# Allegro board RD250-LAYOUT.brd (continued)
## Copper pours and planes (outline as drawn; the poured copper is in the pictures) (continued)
SIG00440 on BOTTOM: 262.6,86.25 262.49,86.29 262.45,86.4 262.45,91.15 262.39,91.21 262.36,91.25 262.35,91.31 262.35,91.9 262.39,92.01 262.5,92.05 263.25,92.05 263.36,92.01 263.4,91.9 263.4,91.25 263.76,90.89 264.45,90.89 264.56,90.84 264.6,90.74 264.6,88.76 264.59,88.7 264.56,88.66 263.6,87.7 263.6,86.4 263.56,86.29 263.45,86.25
SIG00445 on TOP: 254.15,80.9 254.04,80.94 254,81.05 254,83.6 251.9,85.7 247.36,85.7 247.3,85.71 247.26,85.74 245.04,87.96 245.01,88 245,88.06 245,94.29 245.01,94.35 245.04,94.39 246.71,96.06 246.75,96.09 246.81,96.1 261.05,96.1 261.16,96.06 261.2,95.95 261.2,91.55 261.16,91.44 261.05,91.4 258.2,91.4 257.25,90.45 257.25,89.8 257.21,89.69 257.1,89.65 254.8,89.65 254.5,89.35 254.5,87.25 255.06,86.69 255.09,86.65 255.1,86.59 255.1,81.05 255.06,80.94 254.95,80.9
SIG00446 on TOP: 244.85,98 244.74,98.04 244.7,98.15 244.7,105 244.74,105.11 244.85,105.15 255.65,105.15 255.76,105.11 255.8,105 255.8,99.8 256.15,99.45 258.21,99.45 259.45,100.12 259.69,100.22 259.95,100.25 261.3,100.25 262.35,99.2 261.3,98.15 259.95,98.15 259.69,98.18 259.45,98.28 258.21,98.95 256.15,98.95 255.8,98.6 255.8,98.15 255.76,98.04 255.65,98
SIG00446 on BOTTOM: 271.06,95.8 271,95.81 270.96,95.84 268.9,97.9 245.36,97.9 245.3,97.91 245.26,97.94 244.59,98.61 244.56,98.65 244.55,98.71 244.55,103.24 244.56,103.3 244.59,103.34 246.36,105.11 246.4,105.14 246.46,105.15 279.54,105.15 279.6,105.14 279.64,105.11 281.41,103.34 281.44,103.3 281.45,103.24 281.45,97.16 281.44,97.1 281.41,97.06 280.19,95.84 280.15,95.81 280.09,95.8
SIG00447 on TOP: 248.16,107.1 248.1,107.11 248.06,107.14 246.29,108.91 246.26,108.95 246.25,109.01 246.25,112.74 246.26,112.8 246.29,112.84 248.01,114.56 248.05,114.59 248.11,114.6 252.6,114.6 254.05,116.05 254.05,117.35 254.09,117.46 254.2,117.5 255,117.5 255.11,117.46 255.15,117.35 255.15,115.1 257.55,112.7 261.05,112.7 261.16,112.66 261.2,112.55 261.2,107.85 261.16,107.74 261.05,107.7 252.2,107.7 251.64,107.14 251.6,107.11 251.54,107.1
SIG00447 on BOTTOM: 248.46,106.7 248.4,106.71 248.36,106.74 245.99,109.11 245.96,109.15 245.95,109.21 245.95,112.84 245.96,112.9 245.99,112.94 247.21,114.16 247.25,114.19 247.31,114.2 253.29,114.2 253.35,114.19 253.39,114.16 255.15,112.4 261.05,112.4 261.16,112.36 261.2,112.25 261.2,106.85 261.16,106.74 261.05,106.7
SIG00448 on TOP: 244.8,59.95 244.69,59.99 244.65,60.1 244.65,66.9 244.69,67.01 244.8,67.05 255.65,67.05 255.76,67.01 255.8,66.9 255.8,61.75 256.2,61.35 258.21,61.35 259.45,62.02 259.69,62.12 259.95,62.15 261.3,62.15 262.35,61.1 261.3,60.05 259.95,60.05 259.69,60.08 259.45,60.18 258.21,60.85 256.2,60.85 255.8,60.45 255.8,60.1 255.76,59.99 255.65,59.95
SIG00449 on BOTTOM: 262.5,106.65 262.39,106.69 262.35,106.8 262.35,107.65 262.39,107.76 262.5,107.8 264.95,107.8 265.06,107.76 265.1,107.65 265.1,106.8 265.06,106.69 264.95,106.65
SIG00449 on BOTTOM: 262.35,113.4 262.24,113.44 262.2,113.55 262.2,116.8 262.24,116.91 262.35,116.95 262.94,116.95 263,116.94 263.04,116.91 265.01,114.94 265.04,114.9 265.05,114.84 265.05,113.55 265.01,113.44 264.9,113.4
SIG00449 on CONDUCTIVE3, CONDUCTIVE4: 262.45,107 262.38,107.03 262.35,107.1 262.35,115 262.38,115.07 262.45,115.1 265.05,115.1 265.12,115.07 265.15,115 265.15,112.95 265.12,112.88 265.05,112.85 264.05,112.85 263.35,112.15 264.05,111.45 265.05,111.45 265.12,111.42 265.15,111.35 265.15,107.1 265.12,107.03 265.05,107
SIG00450 on BOTTOM: 262.35,75.3 262.24,75.34 262.2,75.45 262.2,78.7 262.24,78.81 262.35,78.85 262.94,78.85 263,78.84 263.04,78.81 265.01,76.84 265.04,76.8 265.05,76.74 265.05,75.45 265.01,75.34 264.9,75.3
SIG00450 on BOTTOM: 262.5,68.55 262.39,68.59 262.35,68.7 262.35,69.55 262.39,69.66 262.5,69.7 264.95,69.7 265.06,69.66 265.1,69.55 265.1,68.7 265.06,68.59 264.95,68.55
SIG00450 on CONDUCTIVE3, CONDUCTIVE4: 262.45,68.9 262.38,68.93 262.35,69 262.35,76.9 262.38,76.97 262.45,77 265.05,77 265.12,76.97 265.15,76.9 265.15,74.35 265.12,74.28 265.05,74.25 264.05,74.25 263.35,73.55 264.05,72.85 265.05,72.85 265.12,72.82 265.15,72.75 265.15,69 265.12,68.93 265.05,68.9
SIG00454 on BOTTOM: 254.05,119.85 253.94,119.89 253.9,120 253.9,122.19 253.91,122.25 253.94,122.29 256.25,124.6 256.25,127.6 256.29,127.71 256.4,127.75 257.4,127.75 257.51,127.71 257.55,127.6 257.55,126.35 258.31,125.59 258.34,125.55 258.35,125.49 258.35,124.76 258.34,124.7 258.31,124.66 258,124.35 258,120 257.96,119.89 257.85,119.85
SIG00455 on BOTTOM: 254.05,81.75 253.94,81.79 253.9,81.9 253.9,84.09 253.91,84.15 253.94,84.19 256.25,86.5 256.25,89.5 256.29,89.61 256.4,89.65 257.4,89.65 257.51,89.61 257.55,89.5 257.55,88.25 258.31,87.49 258.34,87.45 258.35,87.39 258.35,86.66 258.34,86.6 258.31,86.56 258,86.25 258,81.9 257.96,81.79 257.85,81.75
SIG00456 on BOTTOM: 256.9,113.55 256.79,113.59 256.75,113.7 256.75,116.15 255.6,117.3 254.4,117.3 254.29,117.34 254.25,117.45 254.25,117.7 254.29,117.81 254.4,117.85 255.8,117.85 256.46,118.51 256.5,118.54 256.56,118.55 257.65,118.55 257.76,118.51 257.8,118.4 257.8,118.26 257.79,118.2 257.76,118.16 257.55,117.95 257.55,115.1 258.11,114.54 258.14,114.5 258.15,114.44 258.15,113.7 258.11,113.59 258,113.55
SIG00457 on TOP: 254.15,119 254.04,119.04 254,119.15 254,121.7 251.9,123.8 247.36,123.8 247.3,123.81 247.26,123.84 245.04,126.06 245.01,126.1 245,126.16 245,132.39 245.01,132.45 245.04,132.49 246.71,134.16 246.75,134.19 246.81,134.2 261.05,134.2 261.16,134.16 261.2,134.05 261.2,129.65 261.16,129.54 261.05,129.5 258.2,129.5 257.25,128.55 257.25,127.9 257.21,127.79 257.1,127.75 254.8,127.75 254.5,127.45 254.5,125.35 255.06,124.79 255.09,124.75 255.1,124.69 255.1,119.15 255.06,119.04 254.95,119
SIG00458 on TOP: 258.65,115.5 258.54,115.54 258.5,115.65 258.5,120.85 258.54,120.96 258.65,121 259.54,121 259.6,120.99 259.64,120.96 260.1,120.5 269.75,120.5 271.4,122.15 271.4,130.54 271.41,130.6 271.44,130.64 272.36,131.56 272.4,131.59 272.46,131.6 274.7,131.6 274.81,131.56 274.85,131.45 274.85,121.16 274.84,121.1 274.81,121.06 270.69,116.94 270.65,116.91 270.59,116.9 261.05,116.9 259.69,115.54 259.65,115.51 259.59,115.5
SIG00459 on BOTTOM: 253.04,80.45 252.94,80.47 252.86,80.52 252.62,80.79 252.6,80.89 252.6,84.6 251.06,86.14 244.56,86.14 244.5,86.15 244.46,86.18 244.39,86.25 244.36,86.29 244.35,86.35 244.35,86.91 244.39,87.02 244.5,87.06 251.62,87.06 251.71,87.04 251.79,86.99 253.38,85.4 253.43,85.32 253.45,85.22 253.49,85.15 253.5,85.08 253.5,81.5 254,81 254.8,81 254.98,80.93 255.05,80.75 255.05,80.7 254.98,80.52 254.8,80.45
SIG00461 on TOP: 273.06,77 273,77.01 272.96,77.04 271.2,78.8 261.05,78.8 259.69,77.44 259.65,77.41 259.59,77.4 258.65,77.4 258.54,77.44 258.5,77.55 258.5,82.75 258.54,82.86 258.65,82.9 259.44,82.9 259.5,82.89 259.54,82.86 261.65,80.75 268.85,80.75 270.6,82.5 270.6,87.2 270.64,87.31 270.75,87.35 274.65,87.35 274.76,87.31 274.8,87.2 274.8,77.15 274.76,77.04 274.65,77
SIG00512 on BOTTOM: 254.08,10.12 254.04,10.13 253.74,10.18 251.6,10.18 251.54,10.19 251.49,10.22 251.17,10.54 251.14,10.59 251.12,10.65 251.12,10.75 251.06,11.07 251.05,11.12 251.05,11.48 251.06,11.53 251.12,11.85 251.06,12.17 251.05,12.22 251.05,12.58 251.06,12.63 251.12,12.95 251.12,13.18 251.11,13.27 251.1,13.32 251.1,13.5 251.32,13.72 251.55,13.5 251.55,13.32 251.54,13.27 251.47,12.95 251.47,12.72 251.49,12.63 251.5,12.58 251.5,12.22 251.49,12.17 251.43,11.85 251.49,11.53 251.5,11.48 251.5,11.12 251.49,11.07 251.43,10.75 251.43,10.71 251.66,10.47 253.74,10.47 254.04,10.52 254.08,10.53 254.84,10.53 255.04,10.32 254.84,10.12
SIG00526 on TOP: 252.35,4.4 252.24,4.44 252.2,4.55 252.2,7.09 252.21,7.15 252.24,7.19 252.36,7.31 252.4,7.34 252.46,7.35 254.19,7.35 254.25,7.34 254.29,7.31 255.01,6.59 255.04,6.55 255.05,6.49 255.05,5.16 255.04,5.1 255.01,5.06 254.39,4.44 254.35,4.41 254.29,4.4
SIG00789 on BOTTOM: 237.3,5.53 237.07,5.75 237.3,5.97 237.38,5.97 237.7,5.9 238.01,5.9 238.32,6.21 238.36,6.23 238.39,6.25 238.43,6.25 238.75,6.25 239.05,6.3 239.11,6.3 239.18,6.34 239.25,6.35 239.43,6.35 239.48,6.34 239.8,6.28 240.15,6.28 240.21,6.26 240.48,6.01 240.48,5.79 240.27,5.79 240.09,5.97 239.8,5.97 239.48,5.91 239.43,5.9 239.08,5.9 239.05,5.9 238.75,5.95 238.49,5.95 238.18,5.64 238.14,5.62 238.11,5.6 238.07,5.6 237.7,5.6 237.38,5.53
SIG00794 on BOTTOM: 237.17,6.88 237.17,6.91 237.18,6.95 237.17,6.99 237.17,7.02 237.17,7.07 237.24,7.15 237.35,7.17 237.68,7.1 237.91,7.1 238.32,7.51 238.37,7.54 238.43,7.55 238.8,7.55 238.91,7.66 238.95,7.69 239.01,7.7 239.49,7.7 239.55,7.69 239.59,7.66 239.7,7.55 239.82,7.55 240.15,7.62 240.2,7.62 240.38,7.62 240.6,7.4 240.38,7.17 240.2,7.17 240.15,7.18 239.82,7.25 238.49,7.25 238.08,6.84 238.03,6.81 237.97,6.8 237.68,6.8 237.35,6.73 237.24,6.75 237.17,6.83
SIG00797 on TOP: 214.6,4.8 214.49,4.84 214.45,4.95 214.45,7.5 214.24,7.71 214.21,7.75 214.2,7.81 214.2,7.99 214.21,8.05 214.24,8.09 214.75,8.6 214.75,8.84 214.76,8.9 214.79,8.94 215.46,9.61 215.5,9.64 215.56,9.65 216.39,9.65 216.45,9.64 216.49,9.61 216.81,9.29 216.84,9.25 216.85,9.19 216.85,8.41 216.84,8.35 216.81,8.31 216.3,7.8 216.3,4.95 216.26,4.84 216.15,4.8
SIG00817 on BOTTOM: 119.84,54.93 119.77,54.93 119.45,54.88 119.41,54.88 119.22,54.88 119,55.1 119.22,55.33 119.41,55.33 119.45,55.32 119.79,55.26 119.84,55.26 121.81,56.65 121.87,56.68 121.94,56.67 122.01,56.62 122.04,56.53 122.02,56.46 121.98,56.41 121.29,55.92 121.29,54.28 121.98,53.79 122.02,53.74 122.04,53.67 122.01,53.58 121.94,53.53 121.87,53.52 121.81,53.55
SIG00818 on BOTTOM: 177.25,49.69 176.09,50.85 175.14,50.52 174.82,50.68 174.97,50.99 178.15,52.1 179.35,53.31 179.4,53.34 179.46,53.35 179.6,53.35 179.71,53.31 179.75,53.2 179.75,53.06 179.74,53 179.71,52.95 178.5,51.75 177.39,48.57 177.08,48.42 176.92,48.74
SIG00819 on BOTTOM: 134.31,74.42 135.14,74.96 135.14,76.24 134.31,76.78 134.27,76.81 134.25,77.14 134.58,77.2 136.66,75.85 137.05,75.85 137.16,75.81 137.2,75.7 137.2,75.5 137.16,75.39 137.05,75.35 136.66,75.35 134.58,74 134.25,74.06 134.27,74.39
SIG00837 on TOP: 242.91,27.15 242.85,27.16 242.81,27.19 240.05,29.95 237.9,29.95 237.79,29.99 237.75,30.1 237.75,34.3 237.79,34.41 237.9,34.45 240.55,34.45 242.86,36.76 242.9,36.79 242.96,36.8 245.55,36.8 245.66,36.76 245.7,36.65 245.7,27.3 245.66,27.19 245.55,27.15
SIG00839 on TOP: outline of 90 points within 186.2,44.11 194.68,55.75
SIG00843 on BOTTOM: 215.15,8.63 215.16,8.68 215.22,9 215.22,12.83 215.1,12.96 214.9,12.96 214.87,12.96 214.26,12.96 214.2,12.97 214.16,13 214,13.16 213.97,13.2 213.96,13.26 213.96,13.57 213.8,13.72 212.1,13.72 211.78,13.66 211.73,13.65 211.55,13.65 211.32,13.88 211.55,14.1 211.73,14.1 211.78,14.09 212.1,14.03 214.18,14.03 214.35,14.12 214.55,14.16 214.87,14.16 215.01,14.14 215.15,14.09 215.87,13.71 216.14,13.71 217.47,15.04 217.74,16.05 217.75,16.08 217.92,16.16 218.03,16.01 218.03,15.97 217.92,15.54 218.19,15.27 218.62,15.38 218.66,15.38 218.81,15.27 218.73,15.1 218.7,15.09 217.69,14.82 215.53,12.66 215.53,9 215.59,8.68 215.6,8.63 215.6,8.45 215.38,8.22 215.15,8.45
SIG00847 on BOTTOM: 198.37,17.12 198.24,17.24 198.21,17.29 198.2,17.35 198.2,21.15 198.21,21.21 198.54,21.56 198.56,21.57 198.8,21.74 198.8,24.5 198.84,24.61 198.95,24.65 202.34,24.65 202.4,24.64 202.44,24.61 204.71,22.34 204.74,22.3 204.75,22.24 204.75,20.76 204.74,20.7 204.71,20.66 204,19.95 204,19.06 203.99,19 203.96,18.96 203.29,18.29 203.25,18.26 203.19,18.25 198.95,18.25 198.84,18.29 198.8,18.4 198.8,21.16 198.74,21.2 198.61,21.2 198.5,21.09 198.5,17.41 198.58,17.33 198.93,17.14 199,16.97 198.86,16.86 198.84,16.86 198.84,16.84 198.73,16.7 198.56,16.77
SIG00852 on TOP: 248.51,21.8 248.45,21.81 248.41,21.84 247.64,22.61 247.61,22.65 247.6,22.71 247.6,39.69 247.61,39.75 247.64,39.79 248.21,40.36 248.25,40.39 248.31,40.4 258.44,40.4 258.5,40.39 258.54,40.36 259.86,39.04 259.89,39 259.9,38.94 259.9,32.3 259.86,32.19 259.75,32.15 258.15,32.15 256.65,30.65 256.65,22.56 256.64,22.5 256.61,22.46 255.99,21.84 255.95,21.81 255.89,21.8
SIG00852 on BOTTOM: 250.7,22.25 250.59,22.29 250.55,22.4 250.55,23.99 250.56,24.05 250.59,24.09 250.91,24.41 250.95,24.44 251.01,24.45 256.54,24.45 256.6,24.44 256.64,24.41 257.31,23.74 257.34,23.7 257.35,23.64 257.35,22.4 257.31,22.29 257.2,22.25
SIG00853 on BOTTOM: 190.85,12.4 190.75,12.42 190.67,12.47 186.87,16.27 186.82,16.35 186.8,16.45 186.8,23.21 184.76,25.25 184.59,25.31 184.05,25.31 183.05,26.31 184.05,27.31 191.6,27.31 192.1,27.81 192.1,29.7 192.18,30.08 192.39,30.41 194,32.01 195.2,33.49 195.31,33.6 195.35,33.64 196.79,34.8 199.29,37.31 199.62,37.52 200,37.6 217.95,37.6 218.33,37.52 218.66,37.31 219.21,36.75 219.21,35.34 217.8,35.34 217.54,35.6 200.41,35.6 198.2,33.39 197.04,31.95 197,31.91 196.9,31.8 196.86,31.77 195.41,30.6 194.1,29.29 194.1,26.45 194.09,26.29 194.05,26.13 193.83,25.77 193.48,25.52 193.19,25.37 192.86,25.31 186.1,25.31 185.91,25.12 185.91,24.81 187.23,23.49 187.28,23.41 187.3,23.31 187.3,16.55 190.95,12.9 199.9,12.9 201.43,14.43 201.48,14.47 201.54,14.5 201.57,14.5 201.6,14.51 202.98,14.51 203.52,14.58 204.24,14.58 204.56,14.26 204.24,13.93 203.52,13.93 202.98,14.01 201.71,14.01 200.18,12.47 200.1,12.42 200,12.4
SIG00855 on BOTTOM: 214.18,15.95 214.06,15.96 213.95,15.99 212.95,16.4 212.28,16.4 211.95,16.33 211.9,16.32 211.72,16.32 211.5,16.55 211.72,16.77 211.9,16.77 211.95,16.77 212.28,16.7 212.95,16.7 213.95,17.11 214.06,17.14 214.18,17.15 214.55,17.15 215.15,16.55 214.55,15.95
SIG00856 on BOTTOM: 209.1,13.95 208.99,13.99 208.95,14.1 208.95,14.44 208.96,14.5 208.99,14.54 209.35,14.9 209.35,17.05 209.39,17.16 209.5,17.2 210,17.2 210.11,17.16 210.15,17.05 210.15,16.81 210.41,16.71 210.7,16.77 210.75,16.77 210.88,16.77 211.1,16.55 210.88,16.32 210.75,16.32 210.7,16.33 210.41,16.39 210.15,16.29 210.15,15.8 210.4,15.55 211.24,15.55 211.3,15.54 211.34,15.51 211.36,15.49 211.39,15.45 211.4,15.39 211.4,15.06 211.39,15 211.36,14.96 211.34,14.94 211.3,14.91 211.24,14.9 210.7,14.9 210.5,14.7 210.5,14.1 210.46,13.99 210.35,13.95
SIG00858 on TOP: 184.96,54 184.91,54.01 184.86,54.04 184.75,54.15 184.47,54.15 184.45,54.15 184.15,54.15 184.04,54.19 184,54.3 184,55.15 183.94,55.21 183.91,55.25 183.9,55.31 183.9,58.45 183.94,58.56 184.05,58.6 184.6,58.6 184.71,58.56 184.75,58.45 184.75,56.96 184.74,56.9 184.71,56.86 184.6,56.75 184.6,54.54 184.68,54.52 184.78,54.52 184.83,54.51 184.88,54.48 185.06,54.3 185.34,54.3 186.34,55.3 186.34,56.52 186.11,57.05 186.08,57.13 186.07,57.21 186.07,57.83 186.49,58.24 186.9,57.83 186.9,57.21 186.89,57.13 186.87,57.05 186.64,56.52 186.64,55.24 186.63,55.18 185.51,54.04 185.46,54.01 185.4,54
SIG00860 on TOP: 196.06,42.9 196,42.91 195.96,42.94 195.39,43.51 195.36,43.55 195.35,43.61 195.35,47.12 195.36,47.24 195.4,47.35 195.7,47.96 195.7,48.31 195.71,48.36 195.74,48.41 196.39,49.06 196.39,53.83 196.01,54.55 195.96,54.69 195.94,54.83 195.94,55.15 196.54,55.75 197.14,55.15 197.14,54.83 197.13,54.69 197.07,54.55 196.69,53.83 196.69,53.1 196.87,52.92 204.84,52.92 205.75,53.47 205.95,53.55 206.16,53.58 206.55,53.58 207.35,52.77 206.55,51.98 206.16,51.98 205.95,52 204.84,52.62 196.9,52.62 196.69,52.42 196.69,49 196.68,48.94 196,48.24 196,47.96 196.3,47.35 196.34,47.24 196.35,47.12 196.35,47.09 196.37,47.07 196.39,47.06 196.8,46.65 197.75,46.65 197.86,46.61 197.9,46.5 197.9,45.15 198.21,44.84 198.24,44.8 198.25,44.74 198.25,43.05 198.21,42.94 198.1,42.9
SIG00862 on TOP: 189.65,43.93 189.66,43.98 189.72,44.3 189.66,44.62 189.65,44.67 189.65,44.85 189.88,45.08 190.1,44.85 190.1,44.67 190.09,44.62 190.06,44.45 190.95,44.45 191.1,44.6 191.1,45.02 190.8,45.63 190.76,45.74 190.75,45.85 190.75,46.03 190.13,46.33 188.72,46.33 188.62,46.37 187.59,47.4 186.94,47.4 186.83,47.44 186.79,47.55 186.79,48.09 186.83,48.2 186.94,48.24 186.96,48.24 186.96,48.26 187.07,48.4 187.24,48.33 187.43,47.98 188.79,46.62 190.13,46.62 190.75,46.92 190.86,46.96 190.97,46.98 191.25,46.98 191.6,46.83 191.75,46.48 191.75,45.85 191.74,45.74 191.7,45.63 191.4,45.02 191.4,44.6 191.47,44.52 192.03,44.52 192.25,44.3 192.03,44.08 191.85,44.08 191.8,44.08 191.47,44.15 190.06,44.15 190.09,43.98 190.1,43.93 190.1,43.75 189.88,43.52 189.65,43.75
SIG00864 on BOTTOM: 205.9,19 205.79,19.04 205.75,19.15 205.75,19.6 205.79,19.71 205.9,19.75 206.85,19.75 207.61,20.51 207.61,20.57 207.98,21.74 208.02,21.81 208.08,21.87 208.31,21.89 208.47,21.72 208.47,21.65 208.29,21.06 208.5,20.85 209.02,21.02 209.34,20.86 209.18,20.54 207.95,20.16 206.84,19.04 206.79,19.01 206.73,19
SIG007112 on TOP: 209.79,3.19 209.36,3.47 209.33,3.49 209.31,3.51 209.29,3.65 209.4,3.74 209.43,3.74 209.46,3.74 209.46,3.77 209.46,3.8 209.55,3.91 209.69,3.89 209.71,3.87 209.73,3.84 210.01,3.4 212.35,1.06 212.36,1.05 212.38,1.05 216.95,1.05 217.2,1.3 217.2,2.7 217.16,2.75 217.15,2.81 217.15,3.5 217.19,3.61 217.3,3.65 218.99,3.65 219.05,3.64 219.09,3.61 219.41,3.29 219.44,3.25 219.45,3.19 219.45,1.16 219.44,1.1 219.41,1.06 219.14,0.79 219.1,0.76 219.04,0.75 212.38,0.75 212.25,0.78 212.14,0.85
SIG007112 on BOTTOM: 208.4,3.35 208.29,3.39 208.25,3.5 208.25,4.15 208.29,4.26 208.4,4.3 209.34,4.3 209.4,4.29 209.44,4.26 209.76,3.94 209.79,3.9 209.8,3.84 209.8,3.5 209.76,3.39 209.65,3.35
SIG007123 on TOP: 123.5,5.9 123.39,5.94 123.35,6.05 123.35,6.55 123.39,6.66 123.5,6.7 125.35,6.7 125.46,6.66 125.5,6.55 125.5,6.05 125.46,5.94 125.35,5.9
SIG007123 on BOTTOM: 124.51,4.69 124.52,4.74 124.68,5.15 124.4,5.43 124.34,5.36 124.26,5.33 124.22,5.33 124.08,5.37 123.94,5.32 123.83,5.32 123.75,5.39 123.55,5.2 123.67,4.78 123.66,4.69 123.6,4.62 123.56,4.6 123.52,4.59 123.43,4.63 123.38,4.71 123.12,5.67 122.77,6.02 122.74,6.07 122.72,6.12 122.72,6.15 122.66,6.47 122.65,6.52 122.65,6.71 122.59,6.77 122.56,6.82 122.55,6.88 122.55,7.22 122.48,7.55 122.47,7.6 122.47,7.78 122.7,8 122.92,7.78 122.92,7.6 122.92,7.55 122.87,7.31 122.87,7.08 123.06,6.89 123.09,6.85 123.1,6.79 123.1,6.52 123.09,6.47 123.03,6.18 123.33,5.88 124.06,5.69 124.8,5.97 124.8,6.22 124.81,6.27 124.84,6.32 124.95,6.43 125,6.46 125.06,6.47 125.81,6.47 125.87,6.46 125.91,6.43 126.1,6.24 126.43,6.01 126.45,5.99 126.47,5.97 126.49,5.86 126.43,5.76 126.38,5.74 126.36,5.7 126.27,5.63 126.16,5.66 126.13,5.67 126.12,5.69 125.91,5.99 125.45,5.99 125.24,5.79 124.8,4.63 124.78,4.59 124.74,4.56 124.61,4.55 124.51,4.65
SIG007125 on BOTTOM: 207.05,4.7 206.94,4.74 206.9,4.85 206.9,7.35 206.94,7.46 207.05,7.5 208.15,7.5 208.26,7.46 208.3,7.35 208.3,4.85 208.26,4.74 208.15,4.7
SIGN266 on TOP: 166.05,48.59 166.09,48.88 166.21,49.15 166.95,50.31 166.95,51.94 165.46,53.42 164.49,53.42 163.78,53.06 163.65,53.01 163.51,52.99 163.2,52.99 162.85,53.1 162.64,53.4 162.41,54.16 161.66,54.9 153.48,54.9 153.15,54.83 153.1,54.83 152.93,54.83 152.7,55.05 152.93,55.27 153.1,55.27 153.15,55.27 153.48,55.2 162.2,55.2 162.8,55.8 162.8,56.87 160.64,59.03 160.05,59.35 158.44,59.35 158.33,59.39 158.29,59.5 158.29,61.7 158.33,61.81 158.44,61.85 160.64,61.85 160.75,61.81 160.79,61.7 160.79,60.38 161.21,59.6 163.48,57.32 163.57,57.19 163.6,57.04 163.6,55.27 163.78,54.16 163.78,54.09 164.49,53.73 165.53,53.73 165.58,53.71 167.24,52.06 167.25,52 167.25,50.31 167.99,49.15 168.11,48.88 168.15,48.59 168.15,48.1 167.1,47.05 166.05,48.1
SIGN266 on BOTTOM: 158.44,59.35 158.33,59.39 158.29,59.5 158.29,61.7 158.33,61.81 158.44,61.85 160.64,61.85 160.75,61.81 160.79,61.7 160.79,59.5 160.75,59.39 160.64,59.35
SIGN267 on TOP: 123.83,49.67 123.6,49.9 123.83,50.12 124,50.12 124.05,50.12 124.38,50.05 127.69,50.05 128.26,50.63 128.26,50.85 128.16,51.04 128,51.19 127.94,51.4 127.94,59.11 127.84,59.35 127.24,59.35 127.13,59.39 127.09,59.5 127.09,61.7 127.13,61.81 127.24,61.85 127.93,61.85 128.19,62.26 128.19,64.75 128.2,64.81 131.15,67.77 131.15,68.05 130.75,68.47 130.73,68.49 130.72,68.52 130.71,68.55 130.71,68.57 130.77,68.69 130.9,68.71 130.93,68.7 130.96,68.68 131.33,68.3 131.67,68.3 132.04,68.68 132.07,68.7 132.1,68.71 132.23,68.69 132.29,68.57 132.29,68.55 132.28,68.52 132.27,68.49 132.25,68.47 131.61,67.8 128.49,64.69 128.49,62.26 128.75,61.85 129.44,61.85 129.55,61.81 129.59,61.7 129.59,59.5 129.55,59.39 129.44,59.35 128.93,59.35 128.93,53.25 129.1,52.38 129.11,52.33 129.11,52.27 129.11,51.61 129.09,51.47 129.04,51.34 128.66,50.61 128.63,50.57 127.86,49.79 127.81,49.76 127.75,49.75 124.38,49.75 124.05,49.68 124,49.67
SIGN267 on BOTTOM: 127.24,59.35 127.13,59.39 127.09,59.5 127.09,61.7 127.13,61.81 127.24,61.85 129.44,61.85 129.55,61.81 129.59,61.7 129.59,59.5 129.55,59.39 129.44,59.35
VREF_PSFB on BOTTOM: 260.56,10.78 260.39,10.83 260.28,10.96 260.16,11.02 260.13,11.15 260.27,11.67 260.21,11.97 260.2,12.02 260.2,12.2 260.27,12.36 260.43,12.43 260.6,12.43 260.65,12.42 260.98,12.35 261.46,12.35 261.67,12.39 261.72,12.4 261.9,12.4 262.12,12.18 261.9,11.95 261.72,11.95 261.67,11.96 261.35,12.03 260.86,12.03 260.58,11.67 260.66,11.38 261.06,11.38 261.1,11.37 261.15,11.36 261.46,11.26 261.82,11.36 261.87,11.37 261.91,11.36 262,11.29 262.01,11.18 262.04,11.11 262.05,11.04 262.03,11.01 262.01,10.98 261.95,10.86 261.82,10.84 261.54,10.92 261.15,10.79 261.1,10.78 261.06,10.78
VREF_PSFB on CONDUCTIVE3: 252.75,2.55 252.69,2.52 252.49,2.59 252.56,2.79 252.98,2.99 253.44,3.46 253.49,3.49 253.55,3.5 257.84,3.5 260.64,6.31 260.69,6.34 260.75,6.35 261.55,6.35 261.75,6.55 261.75,10.55 261.59,10.99 261.68,11.18 261.88,11.09 261.9,11.03 261.92,11.09 262.12,11.18 262.21,10.99 262.05,10.55 262.05,6.26 264.31,4 265.55,4 265.99,4.16 266.17,4.09 266.13,3.89 266.09,3.87 266.03,3.85 266.09,3.83 266.13,3.81 266.17,3.61 265.99,3.54 265.55,3.7 264.25,3.7 264.19,3.71 264.14,3.74 261.84,6.05 260.81,6.05 258.01,3.24 257.96,3.21 257.9,3.2 253.61,3.2 253.19,2.78 252.99,2.36 252.79,2.29 252.72,2.49

Small or netless copper shapes (teardrops, artwork), in the pictures only: 341 on TOP, 461 on BOTTOM, 12 on CONDUCTIVE2, 61 on CONDUCTIVE3, 34 on CONDUCTIVE4, 9 on CONDUCTIVE5

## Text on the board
Ref Des/Silkscreen Bottom: 1 | 2 | 6 | 7 | 3 | 4 | 5
Ref Des/Silkscreen Top: S | D | 1 | G | A | C | 2 | 6 | 7 | 3 | 4 | 5 | 14 | 12
PAGE_OUTLINE: S | D | 1 | G | A | C | 2 | 6 | 7 | 3 | 4 | 5 | 14 | 12
SYMBOL-2-TOP: CN1 | CN2 | C1 | RV1 | C2 | C3 | L1 | C5 | C8 | C7 | C4 | C6 | R3 | C9 | L2 | L51 | RY1 | D55 | C59 | C51 | R55 | R54 | R58 | R57 | DP404 | D59 | D60 | D61 | D62 | T51 | L52 | Q51 | DP57 | C82 | R56 | L53 | DP58 | DP53 | DP406 | R109 | R108 | DP59 | D103 | Q101 | D56 | DP101 | D102 | R59 | C109 | R110 | DP102 | C54 | D104 | T52 | IC51 | C53 | C105 | Q103 | C104 | C57 | C81 | R64 | C56 | C55 | D65 | Q52 | R121 | C120 | R120 | R119 | R67 | D107 | DP52 | DP103 | D64 | D66 | D67 | DP104 | DP60 | DP54 | C110 | R113 | D111 | C111 | D112 | DP56 | Q102 | DP1 | DP55 | D57 | Q104 | R63 | R62 | R66 | R65 | C61 | D115 | D114 | DP405 | C112 | D116 | DP51 | C52 | R122 | R123 | C412 | D109 | HS2 | HS1 | F401 | C413 | R416 | C410 | R414 | DP407 | D405 | D108 | R415 | R312 | C310 | C307 | C308 | C401 | D404 | D306 | IC302 | C306 | R313 | DP302 | C409 | R401 | Q401 | DP402 | DP403 | C408 | R403 | DP401 | R316 | Q301 | R317 | IC303 | C414 | R351 | Q351 | R353 | CN151 | CN152 | CN202 | CN201 | CN203 | D451 | C451 | CN153 | DP151 | DP154 | R278 | DP258 | D158 | D208 | D207 | D157 | R271 | R275 | R270 | DP157 | R274 | DP203 | R159 | R209 | DP252 | DP201 | DP152 | DP451 | R155 | R205 | DP202 | DP253 | DP153 | DP155 | R211 | R210 | DP156 | R160 | DP257 | R161 | L201 | R213 | R253 | R254 | R255 | R256 | R257 | R258 | R259 | R212 | R162 | R163 | L151 | C501 | C504 | IC501 | C509 | CN504 | R504 | DP501 | C505 | CN502 | CN501 | C502 | Q501 | DP503 | C503 | Q502 | OUTC1 | OUTD1 | BK-F | CK-S | BK-S | CL-F | RD250 | SAA007601010 | SGB007601000 | D305 | R422 | R321 | R320 | R104 | IC101 | C102 | C101 | R97 | R103 | R111 | D105 | R98 | R81 | R82 | R105 | C103 | R112 | D106 | C113 | R51 | R115 | L101 | IC102 | D113 | L54 | R114 | R116 | C114 | IC403 | R417 | C411 | DP304 | CN106 | CN105 | CN104 | CN101 | CN102 | CN103 | IC402 | DP303 | T201 | D403 | T151 | R314 | R315 | R322 | R323 | T401 | T101 | DP251 | DP254 | R352 | R284 | R282 | R277 | Q203 | C205 | Q201 | Q151 | C155 | Q153 | R452 | C154 | C204 | C206 | C156 | C157 | C207 | DP256 | DP255 | CN503 | DP502 | TU-S | TU-F | CL-S | S | D | G | 3 | 1 | A | C | 2 | 5 | 4 | FOR CONTINUED PROTECTION AGAINST RISK OF FIRE. | 6 | 14 | 7 | 12 | REPLACE ONLY WITH SAME TYPE | 250V T15AH | CAUTION
SYMBOL-2-BOTTOM: D1 | C11 | D54 | D52 | C58 | R52 | R53 | R418 | R305 | D302 | D303 | C303 | IC301 | R60 | C60 | R61 | R85 | R308 | R90 | DP61 | R420 | C73 | C74 | R91 | IC52 | D101 | R107 | C65 | R76 | R96 | R68 | R69 | R74 | D110 | R118 | R124 | C121 | C118 | R102 | R423 | R421 | R404 | R405 | R406 | R407 | IC401 | C405 | R408 | C407 | R413 | R309 | R310 | R311 | IC304 | R354 | R357 | R360 | R363 | R365 | R364 | R164 | R165 | R215 | R214 | R454 | R361 | IC451 | R355 | R358 | R201 | R151 | C255 | R276 | R267 | R269 | R453 | R268 | C252 | R260 | C253 | IC251 | IC201 | C153 | C203 | IC151 | C251 | R252 | R273 | C254 | R208 | R204 | D151 | D152 | D154 | D156 | R158 | R154 | D204 | D206 | D201 | D202 | R152 | R153 | R156 | R157 | R261 | R285 | C256 | R206 | R202 | R203 | R207 | R262 | C258 | R292 | R265 | R263 | R280 | C512 | Q504 | R501 | R502 | R503 | Q503 | C508 | A | R6 | Q1 | R5 | R7 | R4 | C311 | Q302 | C78 | C64 | C79 | R318 | Q303 | R319 | IC1 | R2 | R1 | D53 | D51 | R70 | R303 | R71 | R301 | R304 | R302 | D58 | DP301 | C301 | R307 | C302 | R306 | C305 | C304 | D304 | D68 | D63 | C70 | R86 | C67 | R87 | C108 | C66 | R83 | C72 | R89 | C68 | R84 | C71 | R78 | R77 | C76 | C75 | C107 | R88 | C69 | C106 | C62 | R93 | R92 | R94 | R106 | R72 | C119 | R95 | C77 | C63 | R79 | R80 | R73 | C116 | C115 | R101 | C117 | R117 | R419 | R412 | R409 | R410 | R411 | R402 | D401 | C402 | C403 | D402 | C309 | R362 | R359 | R356 | C351 | C159 | C158 | C209 | C208 | C453 | C452 | R251 | C152 | C201 | D251 | R266 | C202 | C151 | R451 | Q154 | Q202 | Q152 | Q204 | D153 | D203 | R272 | C257 | R286 | R287 | R289 | R291 | R281 | R264 | R288 | R290 | R283 | R279 | C507 | C506 | C513 | R505 | R506 | C510 | C511 | 1 | 2 | 6 | 7 | 3 | 4 | 5
User.5: 1 | 2 | 6 | 7 | 3 | 4 | 5
